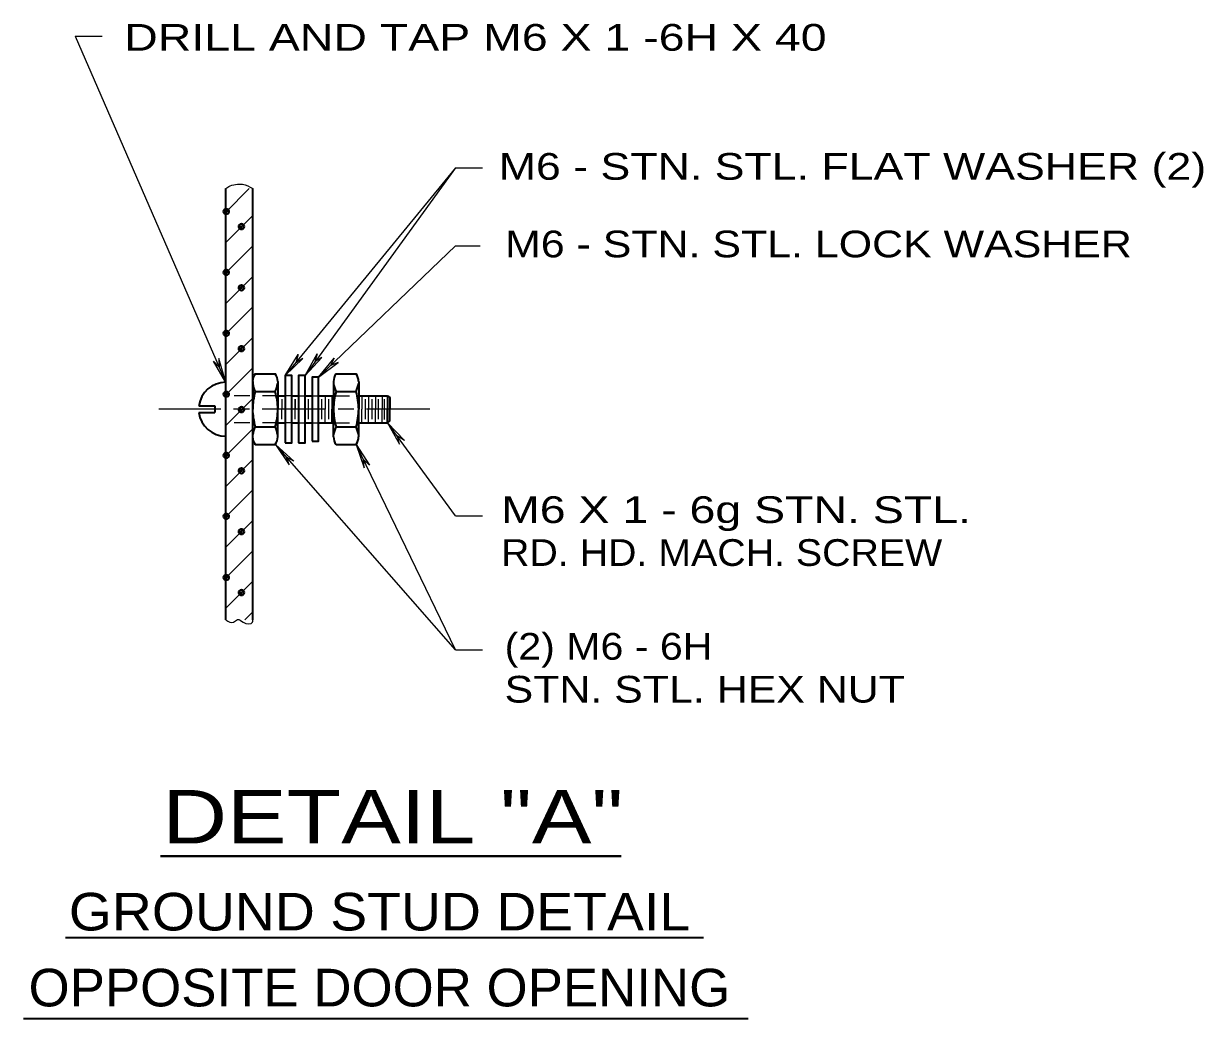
# Model space of a CAD drawing. Extents: x 312583 to 312854, y 144419 to 144597.
# Drawn here: x 312765.12 to 312798.67, y 144464.08 to 144492.38 of the extents above; entities that cross this region are included whole.
import ezdxf
from ezdxf.enums import TextEntityAlignment as Align

# ---------------------------------------------------------------- set-up
doc = ezdxf.new("R2010")
doc.units = 0
doc.header["$LTSCALE"] = 0.3
doc.header["$PDMODE"] = 32
doc.header["$PDSIZE"] = 0.15
doc.linetypes.add('LONG_DASH_SHORT_DASH', pattern=[9.9, 6, -1.2, 1.5, -1.2])
doc.linetypes.add('SHORT_DASHED', pattern=[2.7, 1.5, -1.2])
doc.layers.add('1', color=7, linetype='Continuous', lineweight=40)
doc.layers.add('2', color=7, linetype='Continuous', lineweight=13)

msp = doc.modelspace()

# ---------------------------------------------------------------- linework, layer by layer
at = {"layer": '1', "lineweight": 35}
for p, q in [((312770.8698, 144475.4177), (312770.8698, 144487.6843)), ((312771.6365, 144475.4177), (312771.6365, 144487.6843)), ((312771.7055, 144482.4173), (312772.2805, 144482.4173)), ((312774.0055, 144482.4173), (312774.5805, 144482.4173)), ((312771.6365, 144482.195), (312771.6365, 144481.4053)), ((312771.7055, 144481.9113), (312772.2805, 144481.9113)), ((312772.3495, 144482.195), (312772.3495, 144481.4053)), ((312773.9365, 144482.195), (312773.9365, 144481.4053)), ((312774.0055, 144481.9113), (312774.5805, 144481.9113)), ((312774.6495, 144482.195), (312774.6495, 144481.4053)), ((312772.3648, 144481.7887), (312772.5565, 144481.7887)), ((312772.7481, 144481.7887), (312772.9398, 144481.7887)), ((312773.1238, 144481.7887), (312773.3231, 144481.7887)), ((312773.5071, 144481.7887), (312773.9365, 144481.7887)), ((312774.6495, 144481.7887), (312775.4698, 144481.7887)), ((312775.4698, 144481.7887), (312775.4698, 144481.4053)), ((312770.1031, 144481.505), (312770.5555, 144481.505)), ((312770.1031, 144481.3133), (312770.5555, 144481.3133)), ((312770.5555, 144481.505), (312770.5555, 144481.3133)), ((312771.6365, 144480.6233), (312771.6365, 144481.4053)), ((312772.3495, 144480.6233), (312772.3495, 144481.4053)), ((312773.9365, 144480.6233), (312773.9365, 144481.4053)), ((312774.6495, 144480.6233), (312774.6495, 144481.4053)), ((312775.4698, 144481.022), (312775.4698, 144481.4053)), ((312771.7055, 144480.907), (312772.2805, 144480.907)), ((312772.3648, 144481.022), (312772.5565, 144481.022)), ((312772.7481, 144481.022), (312772.9398, 144481.022)), ((312773.1238, 144481.022), (312773.3231, 144481.022)), ((312773.5071, 144481.022), (312773.9365, 144481.022)), ((312774.0055, 144480.907), (312774.5805, 144480.907)), ((312774.6495, 144481.022), (312775.4698, 144481.022)), ((312771.7055, 144480.401), (312772.2805, 144480.401)), ((312774.0055, 144480.401), (312774.5805, 144480.401))]:
    msp.add_line(p, q, dxfattribs=at)
at = {"layer": '1', "lineweight": 13}
for p, q in [((312770.8698, 144487.0173), (312771.5368, 144487.6843)), ((312770.8698, 144486.151), (312771.6365, 144486.9177)), ((312770.8698, 144485.2847), (312771.6365, 144486.0513)), ((312770.8698, 144484.4183), (312771.6365, 144485.185)), ((312770.8698, 144483.552), (312771.6365, 144484.3187)), ((312770.8698, 144482.678), (312771.6365, 144483.4523)), ((312770.8698, 144481.8193), (312771.6365, 144482.586)), ((312770.8698, 144480.9453), (312771.6365, 144481.712)), ((312770.8698, 144480.079), (312771.6365, 144480.8457)), ((312770.8698, 144479.2127), (312771.6365, 144479.9793)), ((312770.8698, 144478.3463), (312771.6365, 144479.113)), ((312770.8698, 144477.48), (312771.6365, 144478.2467)), ((312770.8698, 144476.6137), (312771.6365, 144477.3803)), ((312770.8698, 144475.7473), (312771.6365, 144476.514)), ((312771.4141, 144475.4177), (312771.6365, 144475.64))]:
    msp.add_line(p, q, dxfattribs=at)
at = {"layer": '1', "linetype": 'SHORT_DASHED', "lineweight": 25}
for p, q in [((312772.3648, 144481.7887), (312770.8698, 144481.7887)), ((312772.7481, 144481.7887), (312772.5565, 144481.7887)), ((312772.9398, 144481.7887), (312773.1238, 144481.7887)), ((312773.3231, 144481.7887), (312773.5071, 144481.7887)), ((312773.9365, 144481.7887), (312774.6495, 144481.7887)), ((312772.3648, 144481.022), (312770.8698, 144481.022)), ((312772.7481, 144481.022), (312772.5565, 144481.022)), ((312772.9398, 144481.022), (312773.1238, 144481.022)), ((312773.3231, 144481.022), (312773.5071, 144481.022)), ((312773.9365, 144481.022), (312774.6495, 144481.022))]:
    msp.add_line(p, q, dxfattribs=at)
at = {"layer": '1', "lineweight": 25}
for p, q in [((312772.4645, 144481.6967), (312772.4645, 144481.4053)), ((312772.8401, 144481.6967), (312772.8401, 144481.4053)), ((312772.8401, 144481.1217), (312772.8401, 144481.6967)), ((312773.2235, 144481.1217), (312773.2235, 144481.6967)), ((312773.6068, 144481.1217), (312773.6068, 144481.6967)), ((312773.6988, 144481.7963), (312773.6988, 144481.4053)), ((312773.7985, 144481.1217), (312773.7985, 144481.6967)), ((312773.8905, 144481.7963), (312773.8905, 144481.4053)), ((312774.7415, 144481.7963), (312774.7415, 144481.4053)), ((312774.8411, 144481.1217), (312774.8411, 144481.6967)), ((312774.9331, 144481.7963), (312774.9331, 144481.4053)), ((312775.0328, 144481.1217), (312775.0328, 144481.6967)), ((312775.1248, 144481.7963), (312775.1248, 144481.4053)), ((312775.2091, 144481.1217), (312775.2091, 144481.6967)), ((312775.3165, 144481.7963), (312775.3165, 144481.4053)), ((312775.3855, 144481.114), (312775.3855, 144481.6967)), ((312772.4645, 144481.1217), (312772.4645, 144481.4053)), ((312772.8401, 144481.1217), (312772.8401, 144481.4053)), ((312773.6988, 144481.022), (312773.6988, 144481.4053)), ((312773.8905, 144481.022), (312773.8905, 144481.4053)), ((312774.7415, 144481.022), (312774.7415, 144481.4053)), ((312774.9331, 144481.022), (312774.9331, 144481.4053)), ((312775.1248, 144481.022), (312775.1248, 144481.4053)), ((312775.3165, 144481.022), (312775.3165, 144481.4053))]:
    msp.add_line(p, q, dxfattribs=at)
at = {"layer": '1', "linetype": 'LONG_DASH_SHORT_DASH', "lineweight": 13}
msp.add_line((312776.6735, 144481.4053), (312768.9685, 144481.4053), dxfattribs=at)
at = {"layer": '1', "lineweight": 35}
for points in [[(312772.5565, 144480.4547), (312772.7481, 144480.4547), (312772.7481, 144482.3713), (312772.5565, 144482.3713)], [(312772.9398, 144480.4547), (312773.1315, 144480.4547), (312773.1315, 144482.3713), (312772.9398, 144482.3713)], [(312773.3231, 144480.5007), (312773.5071, 144480.5007), (312773.5071, 144482.3177), (312773.3231, 144482.3177)]]:
    msp.add_lwpolyline(points, close=True, dxfattribs=at)
for points in [[(312775.4698, 144481.7887), (312775.5388, 144481.7427), (312775.5388, 144481.4053)], [(312775.4698, 144481.022), (312775.5388, 144481.0757), (312775.5388, 144481.4053)]]:
    msp.add_lwpolyline(points, dxfattribs=at)
for centre, radius, start, end in [((312772.0486, 144482.1822), 0.415, 145.8703, 178.33743), ((312771.9343, 144482.1822), 0.415, 1.66257, 34.1297), ((312774.3486, 144482.1822), 0.415, 145.8703, 178.33743), ((312774.2343, 144482.1822), 0.415, 1.66257, 34.1297), ((312770.8678, 144481.4084), 0.7667, 89.85149, 172.64599), ((312772.796, 144482.3826), 1.1883, 191.77014, 203.36365), ((312773.7766, 144481.3562), 2.1446, 164.99798, 178.595), ((312771.1869, 144482.3826), 1.1883, 336.63635, 348.22986), ((312770.2063, 144481.3562), 2.1446, 1.405, 15.00202), ((312775.096, 144482.3826), 1.1883, 191.77014, 203.36365), ((312776.0766, 144481.3562), 2.1446, 164.99798, 178.595), ((312773.4869, 144482.3826), 1.1883, 336.63635, 348.22986), ((312772.5063, 144481.3562), 2.1446, 1.405, 15.00202), ((312770.8678, 144481.4084), 0.7667, 187.12299, 270.14851), ((312773.7766, 144481.4614), 2.1446, 181.405, 195.00202), ((312770.2063, 144481.4614), 2.1446, 344.99798, 358.595), ((312776.0766, 144481.4614), 2.1446, 181.405, 195.00202), ((312772.5063, 144481.4614), 2.1446, 344.99798, 358.595), ((312772.796, 144480.435), 1.1883, 156.63635, 168.22986), ((312771.1869, 144480.435), 1.1883, 11.77014, 23.36365), ((312775.096, 144480.435), 1.1883, 156.63635, 168.22986), ((312773.4869, 144480.435), 1.1883, 11.77014, 23.36365), ((312772.0486, 144480.6354), 0.415, 181.66257, 214.1297), ((312771.9343, 144480.6354), 0.415, 325.8703, 358.33743), ((312774.3486, 144480.6354), 0.415, 181.66257, 214.1297), ((312774.2343, 144480.6354), 0.415, 325.8703, 358.33743)]:
    msp.add_arc(centre, radius, start, end, dxfattribs=at)
at = {"layer": '1', "lineweight": 25}
for points in [[(312770.8698, 144487.6843), (312770.9925, 144487.761), (312771.2071, 144487.807), (312771.3451, 144487.807), (312771.6365, 144487.6843)], [(312770.8698, 144475.4177), (312771.0921, 144475.3487), (312771.2071, 144475.4253), (312771.3681, 144475.3487), (312771.6288, 144475.3487), (312771.6365, 144475.4177)]]:
    msp.add_spline(points, degree=3, dxfattribs=at)
at = {"layer": '1'}
for p in [(312770.8851, 144487.0327), (312771.3145, 144486.6033), (312770.8851, 144485.3), (312771.3145, 144484.863), (312770.8851, 144483.5673), (312771.3145, 144483.1303), (312770.8851, 144481.8347), (312771.3145, 144481.3977), (312770.8851, 144480.0943), (312771.3145, 144479.6573), (312770.8851, 144478.3617), (312771.3145, 144477.9247), (312770.8851, 144476.6213), (312771.3145, 144476.192)]:
    msp.add_point(p, dxfattribs=at)
at = {"layer": '2'}
for p, q in [((312766.5918, 144492.016), (312770.8698, 144482.172)), ((312766.5918, 144492.016), (312767.3585, 144492.016)), ((312777.4018, 144488.2747), (312772.5565, 144482.3713)), ((312777.4018, 144488.2747), (312773.1315, 144482.3713)), ((312777.4018, 144488.2747), (312778.1685, 144488.2747)), ((312777.4018, 144486.059), (312773.5071, 144482.3177)), ((312777.4018, 144486.059), (312778.1075, 144486.059)), ((312772.5565, 144482.3713), (312772.9321, 144482.9617)), ((312772.9321, 144482.9617), (312772.8631, 144482.7317)), ((312773.1315, 144482.3713), (312773.4688, 144482.9847)), ((312773.4688, 144482.9847), (312773.4075, 144482.7547)), ((312770.5171, 144482.7777), (312770.6858, 144482.609)), ((312770.8698, 144482.172), (312770.5171, 144482.7777)), ((312770.6705, 144482.8467), (312770.6858, 144482.609)), ((312770.8698, 144482.172), (312770.6705, 144482.8467)), ((312772.5565, 144482.3713), (312773.0625, 144482.8467)), ((312773.0625, 144482.8467), (312772.8631, 144482.7317)), ((312773.1315, 144482.3713), (312773.6068, 144482.8773)), ((312773.6068, 144482.8773), (312773.4075, 144482.7547)), ((312773.5071, 144482.3177), (312773.9518, 144482.862)), ((312773.5071, 144482.3177), (312774.0668, 144482.7393)), ((312773.9518, 144482.862), (312773.8521, 144482.6473)), ((312774.0668, 144482.7393), (312773.8521, 144482.6473)), ((312777.4018, 144478.377), (312775.4698, 144481.022)), ((312775.4698, 144481.022), (312775.8071, 144480.4163)), ((312775.4698, 144481.022), (312775.9528, 144480.516)), ((312775.8071, 144480.4163), (312775.7535, 144480.6387)), ((312775.9528, 144480.516), (312775.7535, 144480.6387)), ((312777.4018, 144474.5667), (312772.2805, 144480.401)), ((312772.2805, 144480.401), (312772.6715, 144479.826)), ((312772.2805, 144480.401), (312772.8018, 144479.9333)), ((312777.4018, 144474.5667), (312774.5805, 144480.401)), ((312774.5805, 144480.401), (312774.8028, 144479.7417)), ((312774.5805, 144480.401), (312774.9561, 144479.8183)), ((312772.6715, 144479.826), (312772.5948, 144480.0483)), ((312772.8018, 144479.9333), (312772.5948, 144480.0483)), ((312774.8028, 144479.7417), (312774.7875, 144479.9793)), ((312774.9561, 144479.8183), (312774.7875, 144479.9793)), ((312777.4018, 144478.377), (312778.1685, 144478.377)), ((312777.4018, 144474.5667), (312778.1685, 144474.5667))]:
    msp.add_line(p, q, dxfattribs=at)
at = {"layer": '2', "lineweight": 40}
msp.add_line((312769.0162, 144468.6913), (312782.118, 144468.6913), dxfattribs=at)
at = {"layer": '2', "lineweight": 35}
for p, q in [((312766.3129, 144466.3787), (312784.4593, 144466.3787)), ((312765.1218, 144464.0787), (312785.7204, 144464.0787))]:
    msp.add_line(p, q, dxfattribs=at)

# ---------------------------------------------------------------- texts
at = {"layer": '2'}
for s, width, p in [('DRILL AND TAP M6 X 1 -6H X 40', 1.3, (312767.9827, 144491.6068)), ('M6 - STN. STL. FLAT WASHER (2)', 1.25, (312778.6317, 144487.9357)), ('M6 - STN. STL. LOCK WASHER', 1.2, (312778.8124, 144485.7289)), ('M6 X 1 - 6g STN. STL.', 1.3, (312778.6975, 144478.1712)), ('RD. HD. MACH. SCREW', 1.1, (312778.6975, 144476.9512)), ('(2) M6 - 6H', 1.15, (312778.7992, 144474.283)), ('STN. STL. HEX NUT', 1.2, (312778.7992, 144473.063))]:
    msp.add_text(s, height=0.76, dxfattribs=dict(at, width=width)).set_placement(p)
for s, height, width, p in [('DETAIL "A"', 1.52, 1.25, (312775.6213, 144469.0565)), ('GROUND STUD DETAIL', 1.07, 1.1, (312775.2409, 144466.5801)), ('OPPOSITE DOOR OPENING', 1.07, 1.05, (312775.2389, 144464.4204))]:
    msp.add_text(s, height=height, dxfattribs=dict(at, width=width)).set_placement(p, align=Align.CENTER)

doc.saveas('drawing.dxf')
